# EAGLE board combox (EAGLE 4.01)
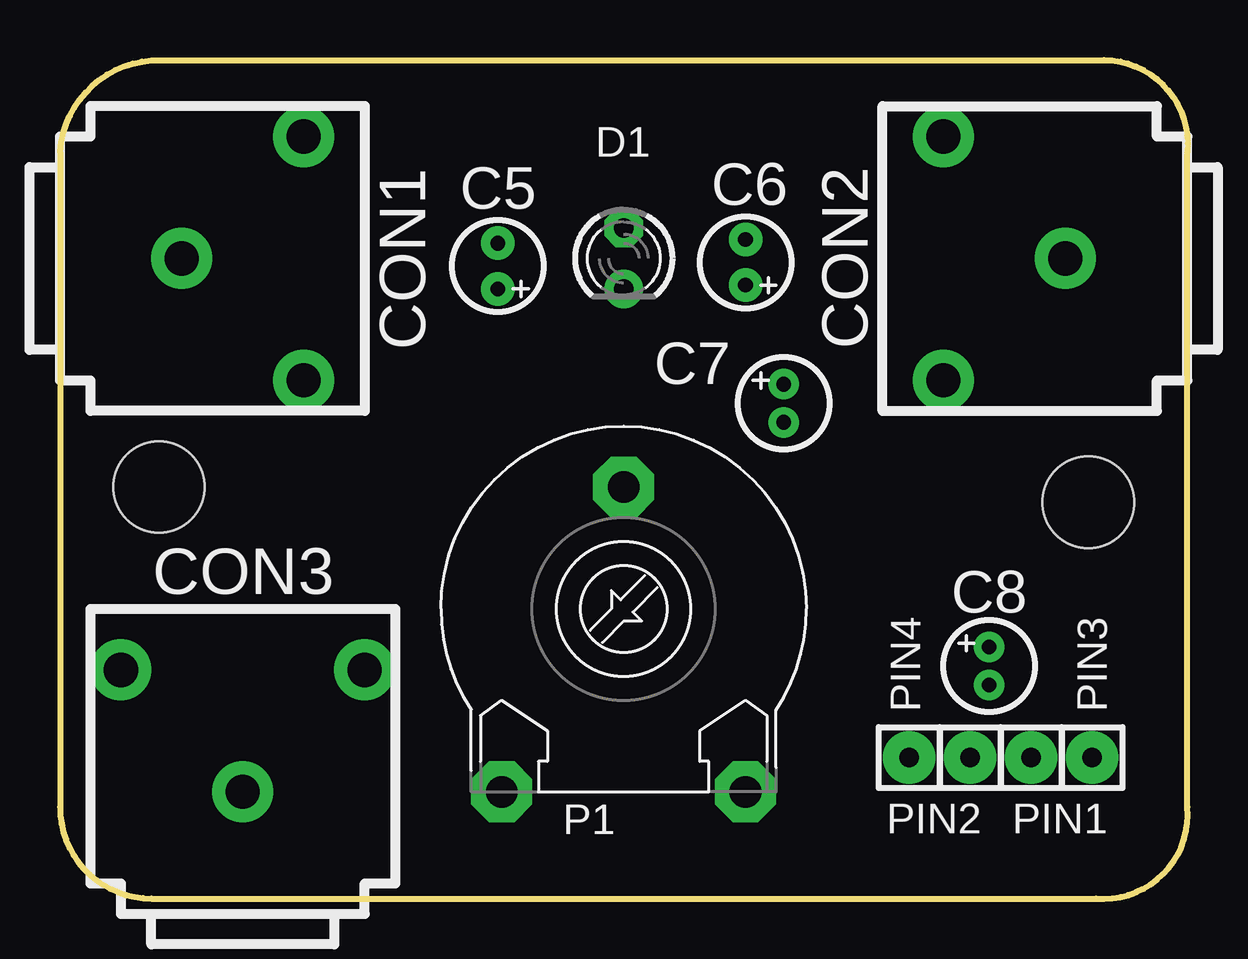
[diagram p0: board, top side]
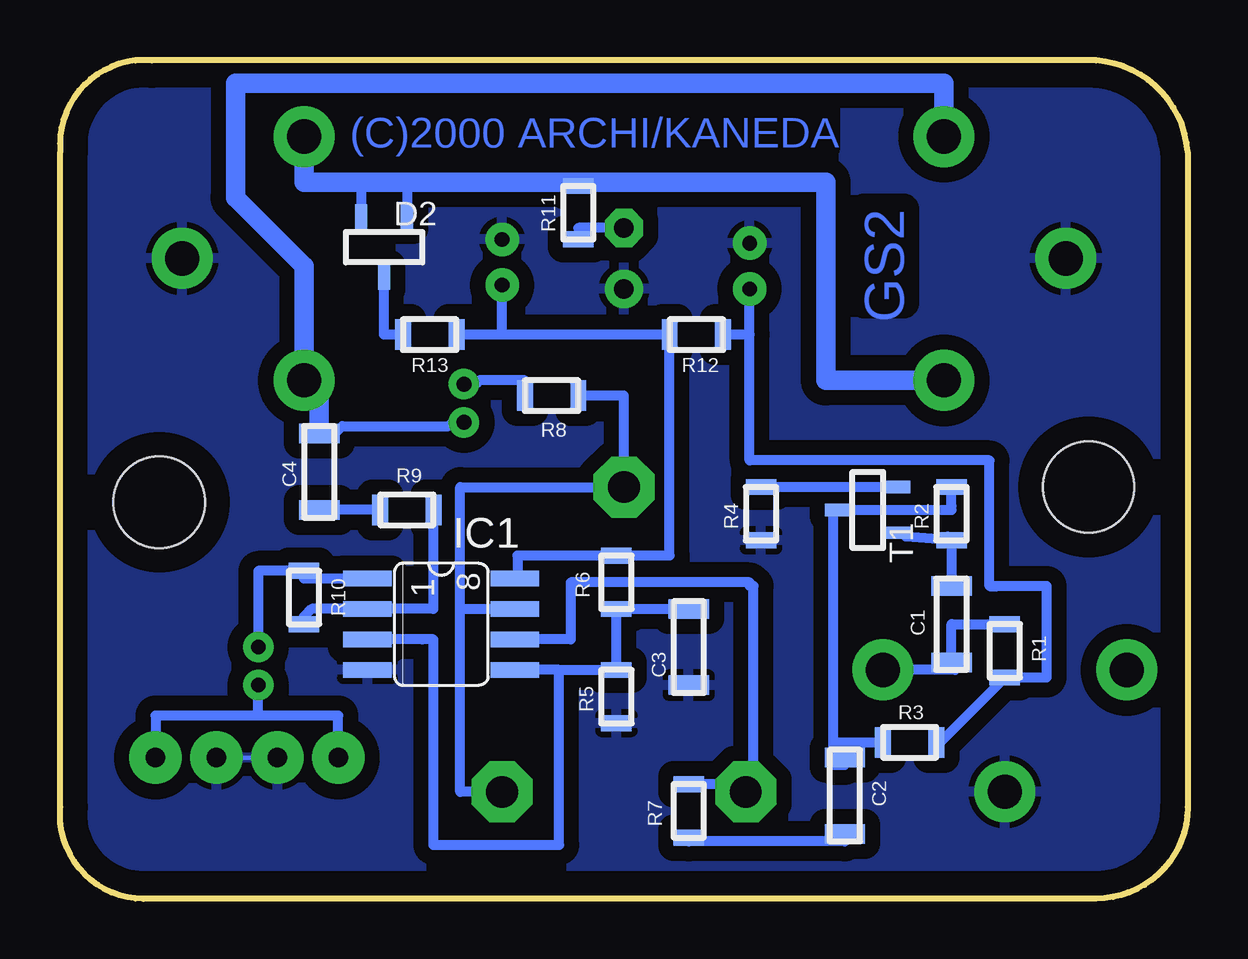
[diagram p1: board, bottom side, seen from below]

Size 47 x 34.95 mm. Coordinates in mm from the lower left corner, seen from the top.
Outline: 0,31.13 arc-81 3.81,34.94 43.18,34.94 arc-100 46.99,31.13 46.99,3.82 arc-100 43.18,0.01 3.81,0.01 arc-90 0,3.82 0,31.13
Copper layers used: Bottom
Net classes: 0 default: width 0.178 mm, clearance 0.61 mm
Holes 3.81 mm at 4.13,17.16 42.86,16.52

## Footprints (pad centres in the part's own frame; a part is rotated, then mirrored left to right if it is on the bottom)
SMD1206 = smd 0.813 x 1.676: P$1 -1.587,0; P$2 1.587,0
C-RM2 = drill 0.61 pad 1.397 round: + -0.953,0; - 0.953,0
C_RM1,5 = drill 0.61 pad 1.27 round: + -0.794,0; - 0.794,0
KLINKE1 = drill 1.422 pad 2.54 round: END -5.08,-5.08; GND 0,0; MIDDLE 5.08,-5.08
LED3 = drill 0.813 pad 1.6 octagon: A -1.27,0 | drill 0.813 pad 1.6 round: K 1.27,0
SMD-TR = smd 0.508 x 1.016: B -0.953,-1.27; C 0,1.27; E 0.953,-1.27
SO-8 = smd 0.66 x 2.032: 1 -1.905,-3.073; 2 -0.635,-3.073; 3 0.635,-3.073; 4 1.905,-3.073; 5 1.905,3.073; 6 0.635,3.073; 7 -0.635,3.073; 8 -1.905,3.073
LI15 = drill 1.321 pad 2.54 octagon: 1 -5.08,-7.62; 2 0,5.08; 3 5.08,-7.62
PIN = drill 0.813 pad 2.184 round: P 0,0
SMD0805 = smd 0.66 x 1.27: P$1 -0.953,0; P$2 1.27,0

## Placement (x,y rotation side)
C1  220nF  [SMD1206]  9.84,11.44 90 bottom
C2  100nF  [SMD1206]  14.29,4.3 270 bottom
C3  100nF  [SMD1206]  20.8,10.49 90 bottom
C4  100nF  [SMD1206]  36.2,17.79 90 bottom
C5  100µF  [C-RM2]  18.26,26.37 90 top
C6  100µF  [C-RM2]  28.57,26.53 90 top
C7  4,7µF  [C_RM1,5]  30.16,20.65 270 top
C8  4,7µF  [C_RM1,5]  38.73,9.7 270 top
CON1  KLIBU1_35  [KLINKE1]  5.08,26.68 90 top
CON2  KLIBU1_35  [KLINKE1]  41.91,26.68 270 top
CON3  KLIBU1_35  [KLINKE1]  7.62,4.46 180 top
D1  grün  [LED3]  23.5,26.68 270 top
D2  BAV70  [SMD-TR]  33.5,27.16 180 bottom
IC1  TL072  [SO-8]  31.11,11.44 270 bottom
P1  500k  [LI15]  23.5,12.08 0 top
PIN1  GND  [PIN]  40.48,5.89 90 top
PIN2  GND  [PIN]  37.94,5.89 90 top
PIN3  R  [PIN]  43.02,5.89 90 top
PIN4  L  [PIN]  35.4,5.89 90 top
R1  5k6  [SMD0805]  7.62,10.49 270 bottom
R2  1M  [SMD0805]  9.84,15.89 90 bottom
R3  10k  [SMD0805]  11.75,6.52 0 bottom
R4  22R  [SMD0805]  17.78,15.89 90 bottom
R5  10k  [SMD0805]  23.81,8.27 90 bottom
R6  10k  [SMD0805]  23.81,13.03 90 bottom
R7  120k  [SMD0805]  20.8,3.51 90 bottom
R8  4k7  [SMD0805]  26.35,20.97 180 bottom
R9  100k  [SMD0805]  32.38,16.21 180 bottom
R10  1M  [SMD0805]  36.83,12.71 270 bottom
R11  820R  [SMD0805]  25.4,28.43 90 bottom
R12  1k  [SMD0805]  20.32,23.51 180 bottom
R13  470R  [SMD0805]  31.43,23.51 180 bottom
T1  BC847C  [SMD-TR]  13.34,16.21 90 bottom

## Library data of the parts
C1-C8 CON1-CON3 IC1 PIN1-PIN4 R1-R13 T1 = ARCHI
D1 = LED
D2 = ARCHI_2
P1 = TRIMPOT

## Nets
+9V: CON1.END CON2.END D2.B D2.E R11.P$2
GND: C3.P$1 C5.- C6.- CON1.GND CON2.GND CON3.GND D1.K IC1.4 PIN1.P PIN2.P R4.P$1 R5.P$1
MICROSUP: C5.+ R1.P$2 R3.P$2 R12.P$1
N$1: C7.+ R8.P$2
N$2: IC1.6 P1.1 R7.P$2
N$3: C8.- PIN3.P PIN4.P
N$4: C2.P$2 R7.P$1
N$5: C1.P$1 CON3.END R1.P$1
N$6: R4.P$2 T1.E
N$7: IC1.7 P1.2 P1.3 R8.P$1
N$8: C1.P$2 R2.P$1 T1.B
N$10: C2.P$1 R2.P$2 R3.P$1 T1.C
N$12: D1.A R11.P$1
N$13: D2.C R13.P$2
N$14: C8.+ IC1.1 R10.P$1
N$15: IC1.2 R9.P$1 R10.P$2
N$16: C4.P$1 R9.P$2
SIGNAL: C4.P$2 C7.- CON1.MIDDLE CON2.MIDDLE
VCC: C6.+ IC1.8 R6.P$2 R12.P$2 R13.P$1
VCC/2: C3.P$2 IC1.3 IC1.5 R5.P$2 R6.P$1

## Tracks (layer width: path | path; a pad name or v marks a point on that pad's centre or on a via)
+9V
  Bottom 0.406: 22.23,29.86 | 22.23,29.86 | 22.23,29.86 25.4,29.86 R11.P$2 | 36.67,31.61 36.67,31.76 CON2.END | D2.B 32.54,29.86 32.38,29.86 | 34.45,29.86 D2.E | 31.43,29.86 32.38,29.86 | 32.38,29.86
  Bottom 0.813: 36.67,31.61 36.83,31.61 36.83,29.86 34.45,29.86 31.43,29.86 22.23,29.86 15.08,29.86 15.08,21.6 CON1.END | 36.67,31.61
GND
  Bottom 0.178: PIN2.P PIN1.P
  pour Bottom (isolate 0.635): 0.32,34.62 46.35,34.62 46.67,34.62 46.67,0.33 0.32,0.33
MICROSUP
  Bottom 0.406: 18.26,23.51 R12.P$1 | 18.26,23.51 18.26,18.27 8.26,18.27 | 18.26,23.51 C5.+ | R1.P$2 | R3.P$2 10.48,6.36 R1.P$2 | 8.26,18.27 | 8.26,13.03 8.26,18.27 | 8.26,13.03 7.94,13.03 | 8.26,13.03 5.87,13.03 5.87,9.22 R1.P$2
N$1
  Bottom 0.178: R8.P$2 27.62,21.6
  Bottom 0.406: 27.62,21.6 29.53,21.6 29.69,21.45 C7.+
N$2
  Bottom 0.406: IC1.6 25.72,10.81 25.72,13.19 18.26,13.19 18.26,13.03 18.1,13.03 18.1,4.46 P1.1 18.41,4.78 R7.P$2
N$3
  Bottom 0.406: PIN4.P 35.4,7.63 38.73,7.63 | 38.73,7.63 43.02,7.63 PIN3.P | 38.73,7.63 C8.-
N$4
  Bottom 0.406: 20.8,2.4 | 20.8,2.4 R7.P$1 | C2.P$2 14.29,2.4 20.8,2.4
N$5
  Bottom 0.406: CON3.END 9.68,9.54 C1.P$1 9.84,11.44 R1.P$1
N$6
  Bottom 0.406: T1.E R4.P$2
N$7
  Bottom 0.406: 29.37,4.46 29.37,4.3 | R8.P$1 23.5,20.97 P1.2 30.32,17.16 30.32,12.08 | P1.3 29.37,4.46 | 29.37,4.46 30.32,4.46 30.32,12.08 | 30.32,12.08 IC1.7 | 30.32,12.08
N$8
  Bottom 0.406: 10,15.1 | 10,15.1 R2.P$1 11.75,15.1 11.91,15.25 T1.B | C1.P$2 R2.P$1 10,15.1
N$9  (via drill 0.81 pad 1.42)
  other vias: 4.13,17.16
N$10
  Bottom 0.406: R2.P$2 9.84,16.37 9.84,16.21 T1.C 14.76,16.21 14.76,6.52 | 14.76,6.52 14.76,5.89 | 14.76,6.52 R3.P$1 | C2.P$1 14.29,5.57 14.76,5.57 14.76,6.52
N$11  (via drill 0.81 pad 1.42)
  other vias: 42.86,16.52
N$12
  Bottom 0.406: D1.A 25.4,27.95 R11.P$1
N$13
  Bottom 0.406: D2.C 33.5,23.51 R13.P$2
N$14
  Bottom 0.178: 36.83,13.35 R10.P$1
  Bottom 0.406: IC1.1 36.83,13.35 | R10.P$1 38.73,13.67 C8.+
N$15
  Bottom 0.406: R10.P$2 36.83,11.76 36.51,12.08 IC1.2 31.43,12.08 R9.P$1
N$16
  Bottom 0.406: R9.P$2 C4.P$1
SIGNAL
  Bottom 0.406: C4.P$2 35.56,19.38 35.24,19.7 30.8,19.7 30.64,19.86 C7.-
  Bottom 0.813: CON1.MIDDLE 10.16,33.99 39.69,33.99 39.69,29.22 36.83,26.37 CON2.MIDDLE 36.83,21.45 36.2,21.45 C4.P$2
VCC
  Bottom 0.406: 28.57,23.51 C6.+ | 28.57,23.51 R13.P$1 | IC1.8 27.94,13.45 27.94,14.3 R6.P$2 21.59,14.3 R12.P$2 28.57,23.51
VCC/2
  Bottom 0.406: C3.P$2 R6.P$1 R5.P$2 26.19,9.54 | 31.43,10.81 IC1.3 | 26.19,9.54 IC1.5 | 26.19,9.54 26.19,2.24 31.43,2.24 31.43,10.81 | 31.43,10.81 31.91,10.81

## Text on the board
Bottom: (C)2000 ARCHI/KANEDA | GS2
tNames: C5 | C6 | C7 | C8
